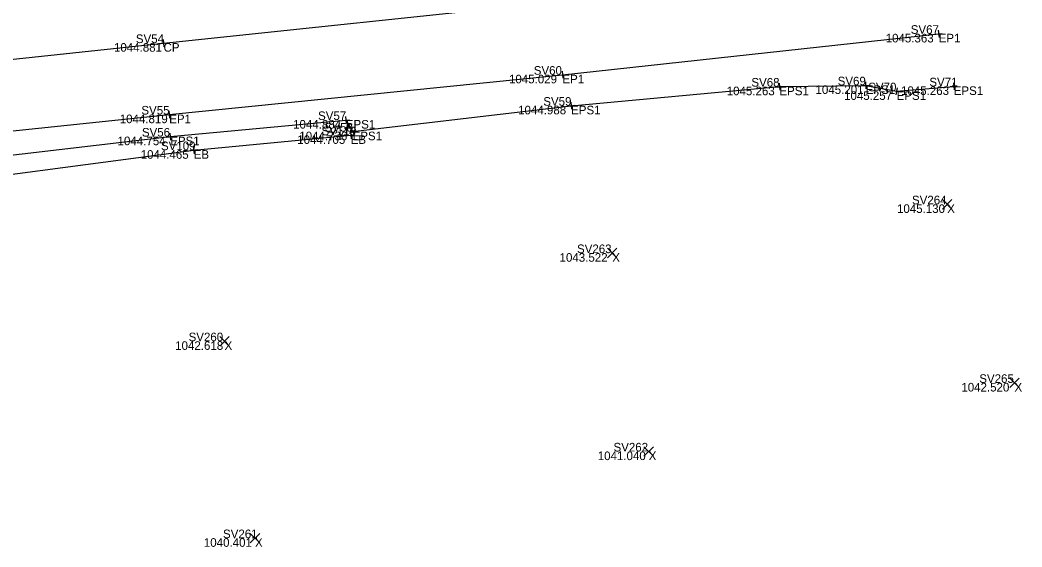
# Model space of a CAD drawing. Extents: x 1542529 to 1609210, y 587215 to 645373.
# Drawn here: x 1609069.9 to 1609209.6, y 645198.3 to 645271.7 of the extents above; entities that cross this region are included whole.
import ezdxf

# ---------------------------------------------------------------- set-up
doc = ezdxf.new("R2010")
doc.units = 0
for name, color, linetype in [('PV_X_COP', 7, 'Continuous'), ('PV_X_EOP', 7, 'Continuous'), ('PV_X_Shoulder', 7, 'Continuous'), ('PV_X_Shoulder_Aggregate', 7, 'Continuous'), ('SV_X_Random_Point', 7, 'Continuous'), ('SV_X_Shot_Marker', 7, 'Continuous'), ('SV_X_Text_Comment', 7, 'Continuous'), ('SV_X_Text_Elevation', 7, 'Continuous'), ('SV_X_Text_Name', 7, 'Continuous')]:
    doc.layers.add(name, color=color, linetype=linetype)

msp = doc.modelspace()

# ---------------------------------------------------------------- linework, layer by layer
at = {"layer": 'PV_X_COP'}
msp.add_lwpolyline([(1608977.96, 645256.77), (1609036.2, 645262.81), (1609089.9, 645268.52), (1609144.66, 645274.29), (1609196.98, 645279.72)], dxfattribs=at)
at = {"layer": 'PV_X_EOP'}
msp.add_lwpolyline([(1608975.06, 645246.73), (1609036.89, 645252.97), (1609090.69, 645258.56), (1609145.51, 645264.11), (1609197.96, 645269.81)], dxfattribs=at)
at = {"layer": 'PV_X_Shoulder'}
msp.add_lwpolyline([(1608973.91, 645242.11), (1609038.4, 645249.35), (1609090.83, 645255.49), (1609115.31, 645257.8), (1609116.26, 645256.18), (1609146.72, 645259.79), (1609175.76, 645262.45), (1609187.79, 645262.63), (1609192.1, 645261.8), (1609200.06, 645262.49)], dxfattribs=at)
at = {"layer": 'PV_X_Shoulder_Aggregate'}
msp.add_lwpolyline([(1608972.98, 645238.86), (1609038.59, 645246.26), (1609094.1, 645253.6), (1609115.99, 645255.67)], dxfattribs=at)
at = {"layer": 'SV_X_Random_Point'}
for p, q in [((1609198.48, 645245.38), (1609199.81, 645246.72)), ((1609198.48, 645246.72), (1609199.81, 645245.38)), ((1609151.78, 645238.58), (1609153.11, 645239.92)), ((1609151.78, 645239.92), (1609153.11, 645238.58)), ((1609097.74, 645226.3), (1609099.07, 645227.64)), ((1609097.74, 645227.64), (1609099.07, 645226.3)), ((1609207.87, 645220.51), (1609209.2, 645221.84)), ((1609207.87, 645221.84), (1609209.2, 645220.51)), ((1609156.87, 645210.95), (1609158.2, 645212.28)), ((1609156.87, 645212.28), (1609158.2, 645210.95)), ((1609101.98, 645198.86), (1609103.32, 645200.19)), ((1609101.98, 645200.19), (1609103.32, 645198.86))]:
    msp.add_line(p, q, dxfattribs=at)
at = {"layer": 'SV_X_Shot_Marker'}
for p, q in [((1609197.46, 645269.75), (1609198.46, 645269.86)), ((1609197.91, 645270.3), (1609198.01, 645269.31)), ((1609197.96, 645269.81), (1609197.96, 645269.81)), ((1609089.4, 645268.47), (1609090.4, 645268.57)), ((1609089.85, 645269.02), (1609089.95, 645268.02)), ((1609089.9, 645268.52), (1609089.9, 645268.52)), ((1609145.01, 645264.06), (1609146.01, 645264.16)), ((1609145.46, 645264.61), (1609145.56, 645263.61)), ((1609145.51, 645264.11), (1609145.51, 645264.11)), ((1609175.71, 645262.95), (1609175.8, 645261.95)), ((1609187.29, 645262.62), (1609188.29, 645262.64)), ((1609187.78, 645263.13), (1609187.79, 645262.13)), ((1609187.79, 645262.63), (1609187.79, 645262.63)), ((1609200.02, 645262.99), (1609200.1, 645261.99)), ((1609175.26, 645262.4), (1609176.25, 645262.49)), ((1609175.76, 645262.45), (1609175.76, 645262.45)), ((1609191.61, 645261.9), (1609192.59, 645261.71)), ((1609192.19, 645262.29), (1609192.01, 645261.31)), ((1609192.1, 645261.8), (1609192.1, 645261.8)), ((1609199.56, 645262.45), (1609200.56, 645262.54)), ((1609200.06, 645262.49), (1609200.06, 645262.49)), ((1609146.23, 645259.73), (1609147.22, 645259.85)), ((1609146.66, 645260.28), (1609146.78, 645259.29)), ((1609090.19, 645258.51), (1609091.19, 645258.61)), ((1609090.64, 645259.06), (1609090.74, 645258.06)), ((1609090.69, 645258.56), (1609090.69, 645258.56)), ((1609146.72, 645259.79), (1609146.72, 645259.79)), ((1609114.81, 645257.75), (1609115.81, 645257.84)), ((1609115.26, 645258.29), (1609115.36, 645257.3)), ((1609115.31, 645257.8), (1609115.31, 645257.8)), ((1609090.77, 645255.99), (1609090.88, 645254.99)), ((1609115.5, 645255.62), (1609116.49, 645255.72)), ((1609116.69, 645256.44), (1609115.83, 645255.93)), ((1609115.95, 645256.17), (1609116.04, 645255.17)), ((1609115.99, 645255.67), (1609115.99, 645255.67)), ((1609116, 645256.61), (1609116.51, 645255.75)), ((1609116.26, 645256.18), (1609116.26, 645256.18)), ((1609090.33, 645255.43), (1609091.32, 645255.55)), ((1609090.83, 645255.49), (1609090.83, 645255.49)), ((1609093.6, 645253.54), (1609094.59, 645253.67)), ((1609094.03, 645254.1), (1609094.16, 645253.11)), ((1609094.1, 645253.6), (1609094.1, 645253.6))]:
    msp.add_line(p, q, dxfattribs=at)

# ---------------------------------------------------------------- texts
at = {"layer": 'SV_X_Text_Comment'}
for s, p in [('EP1', (1609197.96, 645268.61)), ('CP', (1609089.9, 645267.32)), ('EP1', (1609145.51, 645262.91)), ('EPS1', (1609187.79, 645261.43)), ('EPS1', (1609175.76, 645261.25)), ('EPS1', (1609192.1, 645260.6)), ('EPS1', (1609200.06, 645261.29)), ('EP1', (1609090.69, 645257.36)), ('EPS1', (1609146.72, 645258.59)), ('EPS1', (1609115.31, 645256.6)), ('EB', (1609115.99, 645254.47)), ('EPS1', (1609116.26, 645254.98)), ('EPS1', (1609090.83, 645254.29)), ('EB', (1609094.1, 645252.4)), ('X', (1609199.15, 645244.85)), ('X', (1609152.45, 645238.05)), ('X', (1609098.41, 645225.77)), ('X', (1609208.53, 645219.97)), ('X', (1609157.53, 645210.41)), ('X', (1609102.65, 645198.33))]:
    msp.add_text(s, height=1.2, dxfattribs=at).set_placement(p)
at = {"layer": 'SV_X_Text_Elevation'}
for s, p in [('1045.363', (1609190.57, 645268.61)), ('1044.881', (1609082.99, 645267.32)), ('1045.029', (1609138.06, 645262.91)), ('1045.201', (1609180.79, 645261.43)), ('1045.263', (1609168.41, 645261.25)), ('1045.257', (1609184.77, 645260.6)), ('1045.263', (1609192.71, 645261.29)), ('1044.819', (1609083.79, 645257.36)), ('1044.988', (1609139.33, 645258.59)), ('1044.884', (1609107.96, 645256.6)), ('1044.705', (1609108.54, 645254.47)), ('1044.736', (1609108.82, 645254.98)), ('1044.754', (1609083.49, 645254.29)), ('1044.465', (1609086.71, 645252.4)), ('1045.130', (1609192.15, 645244.85)), ('1043.522', (1609145.11, 645238.05)), ('1042.618', (1609091.52, 645225.77)), ('1042.520', (1609201.12, 645219.97)), ('1041.040', (1609150.43, 645210.41)), ('1040.401', (1609095.52, 645198.33))]:
    msp.add_text(s, height=1.2, dxfattribs=at).set_placement(p)
at = {"layer": 'SV_X_Text_Name'}
for s, p in [('SV67', (1609194.07, 645269.81)), ('SV54', (1609086.04, 645268.52)), ('SV60', (1609141.51, 645264.11)), ('SV68', (1609171.85, 645262.45)), ('SV69', (1609183.88, 645262.63)), ('SV70', (1609188.14, 645261.8)), ('SV71', (1609196.66, 645262.49)), ('SV59', (1609142.84, 645259.79)), ('SV55', (1609086.81, 645258.56)), ('SV57', (1609111.44, 645257.8)), ('SV58', (1609112.37, 645256.18)), ('SV56', (1609086.88, 645255.49)), ('SV110', (1609111.92, 645255.67)), ('SV109', (1609089.54, 645253.6)), ('SV264', (1609194.24, 645246.05)), ('SV263', (1609147.54, 645239.25)), ('SV260', (1609093.39, 645226.97)), ('SV265', (1609203.62, 645221.17)), ('SV262', (1609152.63, 645211.61)), ('SV261', (1609098.19, 645199.53))]:
    msp.add_text(s, height=1.2, dxfattribs=at).set_placement(p)

doc.saveas('drawing.dxf')
